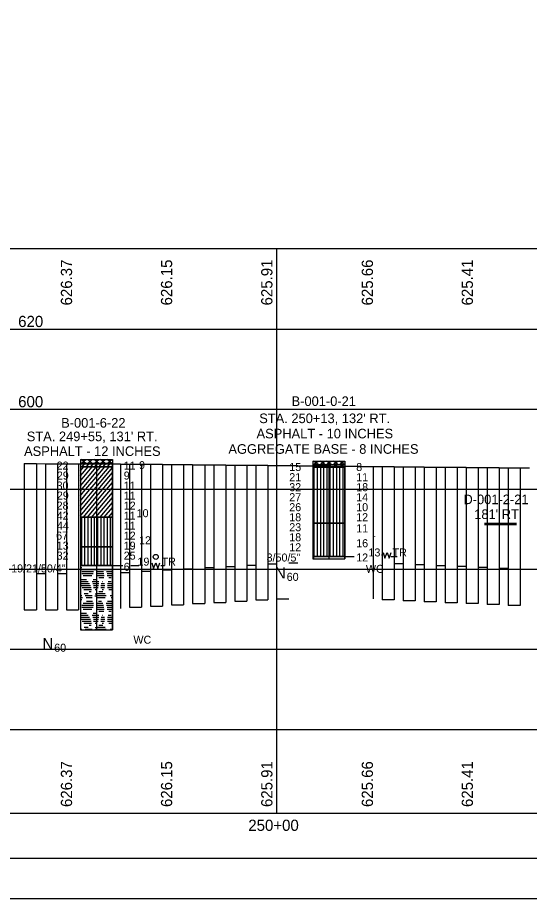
# Model space of a CAD drawing. Extents: x -2280229 to 1306, y -58886 to 440.
# Drawn here: x 120.3 to 248, y 0 to 220 of the extents above; entities that cross this region are included whole.
import ezdxf

# ---------------------------------------------------------------- set-up
doc = ezdxf.new("R2010")
doc.units = 0
for name, color, linetype in [('BR_P_Sub_Deep_Object', 7, 'Continuous'), ('GT_Project_Cells', 7, 'Continuous'), ('GT_Project_Soil_Layers', 7, 'Continuous'), ('GT_Project_Text', 7, 'Continuous'), ('SC_Scratch1', 7, 'Continuous'), ('SC_Scratch2', 7, 'Continuous'), ('SC_Scratch3', 7, 'Continuous'), ('SC_Scratch5', 7, 'Continuous'), ('SC_Scratch9', 7, 'Continuous'), ('SH_Minor_Grid_Line', 7, 'Continuous')]:
    doc.layers.add(name, color=color, linetype=linetype)

msp = doc.modelspace()

# ---------------------------------------------------------------- linework, layer by layer
at = {"layer": 'BR_P_Sub_Deep_Object'}
for p, q in [((121.98, 108.59), (121.98, 72.11)), ((121.98, 108.59), (124.98, 108.59)), ((124.98, 108.59), (124.98, 72.11)), ((124.98, 108.59), (127.23, 108.58)), ((127.23, 108.58), (127.23, 72.11)), ((127.23, 108.58), (130.23, 108.58)), ((130.23, 108.58), (130.23, 72.11)), ((132.48, 108.58), (132.48, 72.11)), ((132.48, 108.58), (135.48, 108.58)), ((135.48, 108.58), (135.48, 72.11)), ((135.48, 108.58), (137.73, 108.58)), ((137.73, 108.55), (140.73, 108.55)), ((140.73, 108.53), (142.98, 108.53)), ((142.98, 108.51), (145.98, 108.51)), ((145.98, 108.51), (145.98, 72.42)), ((145.98, 108.48), (148.23, 108.48)), ((148.23, 108.48), (148.23, 72.72)), ((148.23, 108.46), (151.23, 108.46)), ((151.23, 108.46), (151.23, 72.72)), ((151.23, 108.44), (153.48, 108.44)), ((153.48, 108.44), (153.48, 73.03)), ((153.48, 108.42), (156.48, 108.42)), ((156.48, 108.42), (156.48, 73.03)), ((156.48, 108.39), (158.73, 108.39)), ((158.73, 108.39), (158.73, 73.33)), ((158.73, 108.37), (161.73, 108.37)), ((161.73, 108.37), (161.73, 73.33)), ((161.73, 108.34), (163.98, 108.34)), ((163.98, 108.34), (163.98, 73.64)), ((163.98, 108.32), (166.98, 108.32)), ((166.98, 108.32), (166.98, 73.64)), ((166.98, 108.29), (169.23, 108.29)), ((169.23, 108.29), (169.23, 73.94)), ((169.23, 108.27), (172.23, 108.27)), ((172.23, 108.27), (172.23, 73.94)), ((172.23, 108.24), (174.48, 108.24)), ((174.48, 108.24), (174.48, 74.24)), ((174.48, 108.22), (177.48, 108.22)), ((177.48, 108.22), (177.48, 74.24)), ((177.48, 108.19), (179.73, 108.19)), ((179.73, 108.19), (179.73, 74.55)), ((179.73, 108.17), (182.73, 108.17)), ((182.73, 108.17), (182.73, 74.55)), ((182.73, 108.14), (184.98, 108.14)), ((184.98, 74.85), (184.98, 108.14)), ((184.98, 108.12), (187.98, 108.12)), ((187.98, 108.09), (190.23, 108.09)), ((190.23, 108.07), (193.23, 108.07)), ((193.23, 108.04), (195.48, 108.04)), ((195.48, 108.01), (198.48, 108.01)), ((198.48, 107.98), (200.73, 107.98)), ((200.73, 107.96), (203.73, 107.96)), ((208.98, 107.91), (208.98, 74.8)), ((211.23, 107.88), (211.23, 74.56)), ((211.23, 107.86), (214.23, 107.86)), ((214.23, 107.86), (214.23, 74.56)), ((214.23, 107.83), (216.48, 107.83)), ((216.48, 107.83), (216.48, 74.33)), ((216.48, 107.8), (219.48, 107.8)), ((219.48, 107.8), (219.48, 74.33)), ((219.48, 107.77), (221.73, 107.77)), ((221.73, 107.77), (221.73, 74.1)), ((221.73, 107.75), (224.73, 107.75)), ((224.73, 107.75), (224.73, 74.1)), ((224.73, 107.72), (226.98, 107.72)), ((226.98, 107.72), (226.98, 73.86)), ((226.98, 107.7), (229.98, 107.7)), ((229.98, 107.7), (229.98, 73.86)), ((229.98, 107.67), (232.23, 107.67)), ((232.23, 107.67), (232.23, 73.63)), ((232.23, 107.65), (235.23, 107.65)), ((235.23, 107.65), (235.23, 73.63)), ((235.23, 107.62), (237.48, 107.62)), ((237.48, 107.62), (237.48, 73.39)), ((237.48, 107.6), (240.48, 107.6)), ((240.48, 107.6), (240.48, 73.39)), ((240.48, 107.58), (242.73, 107.58)), ((242.73, 107.58), (242.73, 73.16)), ((242.73, 107.57), (245.73, 107.57)), ((245.73, 107.57), (245.73, 73.16)), ((245.73, 107.55), (247.98, 107.55)), ((187.98, 83.85), (190.23, 83.85)), ((156.48, 82.03), (158.73, 82.03)), ((161.73, 82.33), (163.98, 82.33)), ((166.98, 82.64), (169.23, 82.64)), ((172.23, 82.94), (174.48, 82.94)), ((177.48, 83.24), (179.73, 83.24)), ((182.73, 83.55), (184.98, 83.55)), ((216.48, 83.56), (214.23, 83.56)), ((221.73, 83.33), (219.48, 83.33)), ((226.98, 83.1), (224.73, 83.1)), ((232.23, 82.86), (229.98, 82.86)), ((237.48, 82.63), (235.23, 82.63)), ((242.73, 82.39), (240.48, 82.39)), ((247.98, 82.16), (245.73, 82.16)), ((124.98, 81.11), (127.23, 81.11)), ((130.23, 81.11), (132.48, 81.11)), ((184.98, 74.85), (187.98, 74.85)), ((148.23, 72.72), (151.23, 72.72)), ((153.48, 73.03), (156.48, 73.03)), ((158.73, 73.33), (161.73, 73.33)), ((163.98, 73.64), (166.98, 73.64)), ((169.23, 73.94), (172.23, 73.94)), ((174.48, 74.24), (177.48, 74.24)), ((179.73, 74.55), (182.73, 74.55)), ((214.23, 74.56), (211.23, 74.56)), ((219.48, 74.33), (216.48, 74.33)), ((224.73, 74.1), (221.73, 74.1)), ((229.98, 73.86), (226.98, 73.86)), ((235.23, 73.63), (232.23, 73.63)), ((240.48, 73.39), (237.48, 73.39)), ((245.73, 73.16), (242.73, 73.16)), ((121.98, 72.11), (124.98, 72.11)), ((127.23, 72.11), (130.23, 72.11)), ((132.48, 72.11), (135.48, 72.11))]:
    msp.add_line(p, q, dxfattribs=at)
at = {"layer": 'GT_Project_Cells'}
for points in [[(211.52, 86.42), (211.94, 85.02), (212.49, 86.42), (213.04, 85.02), (213.48, 86.42)], [(153.81, 83.82), (154.23, 82.42), (154.78, 83.82), (155.33, 82.42), (155.77, 83.82)]]:
    msp.add_lwpolyline(points, dxfattribs=at)
msp.add_circle((154.76, 85.31), 0.625, dxfattribs=at)
at = {"layer": 'GT_Project_Soil_Layers'}
for p, q in [((135.98, 108.61), (135.98, 108.61)), ((135.98, 108.5), (136.07, 108.61)), ((135.98, 106.78), (136.85, 107.81)), ((135.98, 105.53), (137.89, 107.81)), ((135.98, 104.29), (138.94, 107.81)), ((136.17, 108.61), (137.33, 109.61)), ((137.33, 108.61), (136.17, 109.61)), ((136.45, 107.81), (136.78, 108.21)), ((136.78, 108.21), (137.12, 108.61)), ((137.49, 107.81), (137.83, 108.21)), ((137.79, 108.61), (138.94, 109.61)), ((138.94, 108.61), (137.79, 109.61)), ((137.83, 108.21), (138.16, 108.61)), ((138.54, 107.81), (138.87, 108.21)), ((138.87, 108.21), (139.21, 108.61)), ((139.4, 108.61), (140.56, 109.61)), ((140.56, 108.61), (139.4, 109.61)), ((139.58, 107.81), (139.92, 108.21)), ((139.92, 108.21), (140.25, 108.61)), ((139.92, 107.73), (139.98, 107.81)), ((139.92, 106.48), (141.03, 107.81)), ((139.92, 105.24), (142.07, 107.81)), ((139.92, 103.99), (143.12, 107.81)), ((140.63, 107.81), (140.96, 108.21)), ((140.96, 108.21), (141.3, 108.61)), ((141.02, 108.61), (142.18, 109.61)), ((142.18, 108.61), (141.02, 109.61)), ((141.67, 107.81), (142.01, 108.21)), ((142.01, 108.21), (142.34, 108.61)), ((142.64, 108.61), (143.79, 109.61)), ((143.79, 108.61), (142.64, 109.61)), ((142.72, 107.81), (143.05, 108.21)), ((143.05, 108.21), (143.39, 108.61)), ((143.76, 107.81), (143.98, 108.07)), ((193.98, 108.41), (193.98, 108.41)), ((194.17, 108.41), (195.33, 109.21)), ((195.33, 108.41), (194.17, 109.21)), ((194.17, 107.71), (195.33, 108.41)), ((195.33, 107.71), (194.17, 108.41)), ((195.79, 108.41), (196.94, 109.21)), ((196.94, 108.41), (195.79, 109.21)), ((195.79, 107.71), (196.94, 108.41)), ((196.94, 107.71), (195.79, 108.41)), ((197.41, 108.41), (198.56, 109.21)), ((198.56, 108.41), (197.41, 109.21)), ((197.41, 107.71), (198.56, 108.41)), ((198.56, 107.71), (197.41, 108.41)), ((199.02, 108.41), (200.18, 109.21)), ((200.18, 108.41), (199.02, 109.21)), ((199.02, 107.71), (200.18, 108.41)), ((200.18, 107.71), (199.02, 108.41)), ((200.64, 108.41), (201.79, 109.21)), ((201.79, 108.41), (200.64, 109.21)), ((200.64, 107.71), (201.79, 108.41)), ((201.79, 107.71), (200.64, 108.41)), ((135.98, 103.05), (139.91, 107.73)), ((135.98, 101.8), (139.91, 106.48)), ((139.92, 102.75), (143.98, 107.6)), ((139.92, 101.51), (143.98, 106.35)), ((193.98, 107.71), (193.98, 107.71)), ((194.32, 100.71), (194.32, 107.71)), ((195.12, 100.71), (195.12, 107.71)), ((195.92, 100.71), (195.92, 107.71)), ((196.72, 100.71), (196.72, 107.71)), ((197.52, 100.71), (197.52, 107.71)), ((198.32, 100.71), (198.32, 107.71)), ((199.12, 100.71), (199.12, 107.71)), ((199.92, 100.71), (199.92, 107.71)), ((200.72, 100.71), (200.72, 107.71)), ((201.52, 100.71), (201.52, 107.71)), ((136.78, 101.51), (139.91, 105.24)), ((137.83, 101.51), (139.91, 103.99)), ((140.96, 101.51), (143.98, 105.11)), ((142.01, 101.51), (143.98, 103.86)), ((135.98, 100.56), (136.78, 101.51)), ((135.98, 99.31), (137.83, 101.51)), ((135.98, 98.07), (138.87, 101.51)), ((135.98, 96.82), (139.92, 101.51)), ((138.87, 101.51), (139.91, 102.75)), ((139.92, 97.77), (143.05, 101.51)), ((139.92, 99.02), (142.01, 101.51)), ((139.92, 100.26), (140.96, 101.51)), ((139.92, 96.53), (143.98, 101.37)), ((143.05, 101.51), (143.98, 102.62)), ((135.98, 95.58), (139.91, 100.26)), ((136.72, 95.21), (139.91, 99.02)), ((139.92, 95.28), (143.98, 100.13)), ((194.32, 93.71), (194.32, 100.71)), ((195.12, 93.71), (195.12, 100.71)), ((195.92, 93.71), (195.92, 100.71)), ((196.72, 93.71), (196.72, 100.71)), ((197.52, 93.71), (197.52, 100.71)), ((198.32, 93.71), (198.32, 100.71)), ((199.12, 93.71), (199.12, 100.71)), ((199.92, 93.71), (199.92, 100.71)), ((200.72, 93.71), (200.72, 100.71)), ((201.52, 93.71), (201.52, 100.71)), ((137.76, 95.21), (139.91, 97.77)), ((140.9, 95.21), (143.98, 98.88)), ((141.94, 95.21), (143.98, 97.64)), ((136.32, 91.51), (136.32, 95.21)), ((137.12, 91.51), (137.12, 95.21)), ((137.92, 91.51), (137.92, 95.21)), ((138.72, 91.51), (138.72, 95.21)), ((138.81, 95.21), (139.91, 96.53)), ((139.52, 91.51), (139.52, 95.21)), ((139.85, 95.21), (139.91, 95.28)), ((140.32, 91.51), (140.32, 95.21)), ((141.12, 91.51), (141.12, 95.21)), ((141.92, 91.51), (141.92, 95.21)), ((142.72, 91.51), (142.72, 95.21)), ((142.99, 95.21), (143.98, 96.4)), ((143.52, 91.51), (143.52, 95.21)), ((194.32, 89.56), (194.32, 93.71)), ((195.12, 89.56), (195.12, 93.71)), ((195.92, 89.56), (195.92, 93.71)), ((196.72, 89.56), (196.72, 93.71)), ((197.52, 89.56), (197.52, 93.71)), ((198.32, 89.56), (198.32, 93.71)), ((199.12, 89.56), (199.12, 93.71)), ((199.92, 89.56), (199.92, 93.71)), ((200.72, 89.56), (200.72, 93.71)), ((201.52, 89.56), (201.52, 93.71)), ((136.32, 87.81), (136.32, 91.51)), ((137.12, 87.81), (137.12, 91.51)), ((137.92, 87.81), (137.92, 91.51)), ((138.72, 87.81), (138.72, 91.51)), ((139.52, 87.81), (139.52, 91.51)), ((140.32, 87.81), (140.32, 91.51)), ((141.12, 87.81), (141.12, 91.51)), ((141.92, 87.81), (141.92, 91.51)), ((142.72, 87.81), (142.72, 91.51)), ((143.52, 87.81), (143.52, 91.51)), ((194.32, 85.41), (194.32, 89.56)), ((195.12, 85.41), (195.12, 89.56)), ((195.92, 85.41), (195.92, 89.56)), ((196.72, 85.41), (196.72, 89.56)), ((197.52, 85.41), (197.52, 89.56)), ((198.32, 85.41), (198.32, 89.56)), ((199.12, 85.41), (199.12, 89.56)), ((199.92, 85.41), (199.92, 89.56)), ((200.72, 85.41), (200.72, 89.56)), ((201.52, 85.41), (201.52, 89.56)), ((136.32, 85.46), (136.32, 87.81)), ((137.12, 85.46), (137.12, 87.81)), ((137.92, 85.46), (137.92, 87.81)), ((138.72, 85.46), (138.72, 87.81)), ((139.52, 85.46), (139.52, 87.81)), ((140.32, 85.46), (140.32, 87.81)), ((141.12, 85.46), (141.12, 87.81)), ((141.92, 85.46), (141.92, 87.81)), ((142.72, 85.46), (142.72, 87.81)), ((143.52, 85.46), (143.52, 87.81)), ((136.32, 83.11), (136.32, 85.46)), ((137.12, 83.11), (137.12, 85.46)), ((137.92, 83.11), (137.92, 85.46)), ((138.72, 83.11), (138.72, 85.46)), ((139.52, 83.11), (139.52, 85.46)), ((140.32, 83.11), (140.32, 85.46)), ((141.12, 83.11), (141.12, 85.46)), ((141.92, 83.11), (141.92, 85.46)), ((142.72, 83.11), (142.72, 85.46)), ((143.52, 83.11), (143.52, 85.46)), ((194.32, 85.04), (193.98, 85.04)), ((136.48, 83.04), (135.98, 83.04)), ((136.32, 82.54), (135.98, 82.54)), ((139.26, 81.54), (136.35, 81.54)), ((139.28, 82.04), (136.66, 82.04)), ((138.95, 83.04), (137.38, 83.04)), ((139.03, 82.17), (137.46, 82.17)), ((141.72, 81.54), (140.05, 81.54)), ((141.56, 82.04), (140.1, 82.04)), ((142.13, 83.04), (140.13, 83.04)), ((141.23, 82.17), (140.45, 82.17)), ((143.98, 82.04), (142.37, 82.04)), ((143.98, 81.54), (142.5, 81.54)), ((143.88, 82.17), (142.72, 82.17)), ((143.98, 83.04), (143.65, 83.04)), ((137.51, 79.54), (136.03, 79.54)), ((139.16, 81.04), (136.37, 81.04)), ((138.86, 80.54), (136.66, 80.54)), ((139.88, 79.54), (139.16, 79.54)), ((140.12, 79.54), (139.88, 79.54)), ((141.85, 81.04), (139.99, 81.04)), ((141.92, 80.54), (139.99, 80.54)), ((141.78, 80.04), (140.55, 80.04)), ((143.98, 81.04), (142.62, 81.04)), ((143.98, 80.54), (142.66, 80.54)), ((143.65, 80.04), (143.1, 80.04)), ((137.93, 79.04), (135.98, 79.04)), ((138.26, 78.54), (135.98, 78.54)), ((138.49, 78.04), (136.12, 78.04)), ((138.65, 77.54), (136.39, 77.54)), ((138.73, 77.04), (136.87, 77.04)), ((139.88, 79.04), (138.93, 79.04)), ((139.88, 78.54), (139.05, 78.54)), ((139.88, 78.04), (139.24, 78.04)), ((139.88, 77.54), (139.25, 77.54)), ((139.88, 77.04), (139.63, 77.04)), ((140.58, 79.04), (139.88, 79.04)), ((140.59, 78.54), (139.88, 78.54)), ((140.48, 78.04), (139.88, 78.04)), ((140.37, 77.54), (139.88, 77.54)), ((140.19, 77.04), (139.88, 77.04)), ((142.06, 78.04), (141.04, 78.04)), ((142.02, 77.54), (141.05, 77.54)), ((141.95, 78.54), (141.17, 78.54)), ((141.72, 77.04), (141.42, 77.04)), ((141.58, 79.04), (141.49, 79.04)), ((143.96, 78.54), (142.72, 78.54)), ((143.98, 77.54), (142.74, 77.54)), ((143.98, 78.04), (142.75, 78.04)), ((143.64, 79.04), (142.9, 79.04)), ((143.98, 77.04), (143.03, 77.04)), ((136.09, 76.04), (135.98, 76.04)), ((136.34, 75.54), (135.98, 75.54)), ((136.48, 75.04), (135.98, 75.04)), ((137.95, 76.04), (136.89, 76.04)), ((138.89, 75.54), (137.13, 75.54)), ((138.95, 75.04), (137.38, 75.04)), ((138.68, 76.54), (138.16, 76.54)), ((139.59, 75.54), (139.88, 75.54)), ((139.65, 76.04), (139.88, 76.04)), ((142.16, 76.04), (139.88, 76.04)), ((142.42, 75.54), (139.88, 75.54)), ((142.13, 75.04), (140.13, 75.04)), ((141.57, 76.54), (140.61, 76.54)), ((143.98, 75.54), (143.38, 75.54)), ((143.98, 75.04), (143.65, 75.04)), ((143.98, 76.04), (143.82, 76.04)), ((136.32, 74.54), (135.98, 74.54)), ((139.26, 73.17), (136.35, 73.17)), ((139.16, 72.67), (136.37, 72.67)), ((139.28, 73.67), (136.66, 73.67)), ((139.03, 74.17), (137.46, 74.17)), ((141.85, 72.67), (139.99, 72.67)), ((141.72, 73.17), (140.05, 73.17)), ((141.56, 73.67), (140.1, 73.67)), ((141.23, 74.17), (140.45, 74.17)), ((143.98, 73.67), (142.37, 73.67)), ((143.98, 73.17), (142.5, 73.17)), ((143.98, 72.67), (142.62, 72.67)), ((143.88, 74.17), (142.72, 74.17)), ((137.93, 70.67), (135.98, 70.67)), ((137.51, 71.17), (136.03, 71.17)), ((138.86, 72.17), (136.66, 72.17)), ((139.88, 70.67), (138.93, 70.67)), ((139.88, 71.17), (139.16, 71.17)), ((140.12, 71.17), (139.88, 71.17)), ((140.58, 70.67), (139.88, 70.67)), ((141.92, 72.17), (139.99, 72.17)), ((141.78, 71.67), (140.55, 71.67)), ((141.58, 70.67), (141.49, 70.67)), ((143.98, 72.17), (142.66, 72.17)), ((143.64, 70.67), (142.9, 70.67)), ((143.65, 71.67), (143.1, 71.67)), ((138.26, 70.17), (135.98, 70.17)), ((138.49, 69.67), (136.12, 69.67)), ((138.65, 69.17), (136.39, 69.17)), ((138.73, 68.67), (136.87, 68.67)), ((139.88, 70.17), (139.05, 70.17)), ((139.88, 69.67), (139.24, 69.67)), ((139.88, 69.17), (139.25, 69.17)), ((139.88, 68.67), (139.63, 68.67)), ((140.59, 70.17), (139.88, 70.17)), ((140.48, 69.67), (139.88, 69.67)), ((140.37, 69.17), (139.88, 69.17)), ((140.19, 68.67), (139.88, 68.67)), ((142.06, 69.67), (141.04, 69.67)), ((142.02, 69.17), (141.05, 69.17)), ((141.95, 70.17), (141.17, 70.17)), ((141.72, 68.67), (141.42, 68.67)), ((143.96, 70.17), (142.72, 70.17)), ((143.98, 69.17), (142.74, 69.17)), ((143.98, 69.67), (142.75, 69.67)), ((143.98, 68.67), (143.03, 68.67)), ((136.09, 67.67), (135.98, 67.67)), ((136.34, 67.17), (135.98, 67.17)), ((137.95, 67.67), (136.89, 67.67)), ((138.89, 67.17), (137.13, 67.17)), ((138.68, 68.17), (138.16, 68.17)), ((139.59, 67.17), (139.88, 67.17)), ((139.65, 67.67), (139.88, 67.67)), ((142.16, 67.67), (139.88, 67.67)), ((142.42, 67.17), (139.88, 67.17)), ((141.57, 68.17), (140.61, 68.17)), ((143.98, 67.17), (143.38, 67.17)), ((143.98, 67.67), (143.82, 67.67))]:
    msp.add_line(p, q, dxfattribs=at)
for points in [[(143.98, 108.61), (135.98, 108.61), (135.98, 107.81), (143.98, 107.81)], [(135.98, 95.21), (143.98, 95.21), (143.98, 107.81), (135.98, 107.81)], [(193.98, 93.71), (201.98, 93.71), (201.98, 107.71), (193.98, 107.71)], [(143.98, 95.21), (135.98, 95.21), (135.98, 87.81), (143.98, 87.81)], [(201.98, 93.71), (193.98, 93.71), (193.98, 85.41), (201.98, 85.41)], [(143.98, 87.81), (135.98, 87.81), (135.98, 83.11), (143.98, 83.11)], [(193.98, 84.81), (201.98, 84.81), (201.98, 85.41), (193.98, 85.41)], [(135.98, 82.11), (143.98, 82.11), (143.98, 83.11), (135.98, 83.11)], [(135.98, 67.11), (143.98, 67.11), (143.98, 82.11), (135.98, 82.11)]]:
    msp.add_lwpolyline(points, close=True, dxfattribs=at)
at = {"layer": 'GT_Project_Text'}
msp.add_lwpolyline([(0, 0), (680, 0), (680, 440), (0, 440)], close=True, dxfattribs=at)
at = {"layer": 'SC_Scratch1'}
msp.add_lwpolyline([(30, 430), (670, 430), (670, 10), (30, 10)], close=True, dxfattribs=at)
at = {"layer": 'SC_Scratch2'}
for p, q in [((130.23, 108.58), (132.48, 108.58)), ((135.98, 109.61), (143.98, 109.61)), ((135.98, 109.61), (135.98, 67.11)), ((135.98, 108.61), (143.98, 108.61)), ((135.98, 107.81), (143.98, 107.81)), ((139.98, 109.61), (139.98, 67.11)), ((143.98, 109.61), (143.98, 67.11)), ((193.98, 109.21), (201.98, 109.21)), ((193.98, 109.21), (193.98, 84.81)), ((193.98, 108.41), (201.98, 108.41)), ((197.98, 109.21), (197.98, 84.81)), ((201.98, 109.21), (201.98, 84.81)), ((201.98, 109.21), (201.98, 84.81)), ((203.73, 107.93), (205.98, 107.93)), ((205.98, 107.91), (208.98, 107.91)), ((208.98, 107.88), (211.23, 107.88)), ((193.98, 107.71), (201.98, 107.71)), ((135.98, 95.21), (143.98, 95.21)), ((193.98, 93.71), (201.98, 93.71)), ((236.8, 93.71), (244.8, 93.71)), ((236.8, 93.41), (244.8, 93.41)), ((240.8, 93.71), (240.8, 93.41)), ((135.98, 87.81), (143.98, 87.81)), ((193.98, 85.41), (201.98, 85.41)), ((193.98, 84.81), (201.98, 84.81)), ((201.98, 85.41), (204.27, 85.41)), ((211.46, 85.71), (211.06, 85.71)), ((135.98, 83.11), (143.98, 83.11)), ((135.98, 82.11), (143.98, 82.11)), ((145.98, 81.42), (148.23, 81.42)), ((148.55, 83.11), (150.53, 83.11)), ((151.23, 81.72), (153.48, 81.72)), ((135.98, 67.11), (143.98, 67.11))]:
    msp.add_line(p, q, dxfattribs=at)
at = {"layer": 'SC_Scratch3'}
for p, q in [((213.45, 85.41), (214.98, 85.41)), ((143.98, 83.11), (146.55, 83.11)), ((156.08, 83.11), (156.98, 83.11)), ((187.44, 81.31), (187.44, 81.31)), ((129.44, 63.61), (129.44, 63.61))]:
    msp.add_line(p, q, dxfattribs=at)
at = {"layer": 'SC_Scratch5'}
for p, q in [((603.01, 162.21), (45.43, 162.21)), ((603.01, 21.22), (45.43, 21.22))]:
    msp.add_line(p, q, dxfattribs=at)
at = {"layer": 'SH_Minor_Grid_Line'}
for p, q in [((184.98, 21.22), (184.98, 162.21)), ((45.43, 142.21), (603.01, 142.21)), ((45.43, 122.21), (603.01, 122.21)), ((45.43, 102.21), (603.01, 102.21)), ((45.43, 82.21), (603.01, 82.21)), ((45.43, 62.21), (603.01, 62.21)), ((45.43, 42.21), (603.01, 42.21))]:
    msp.add_line(p, q, dxfattribs=at)

# ---------------------------------------------------------------- texts
at = {"layer": 'SC_Scratch2'}
for s, height, p in [("STA. 250+13, 132' RT.", 2.4, (180.59, 118.71)), ("STA. 249+55, 131' RT.", 2.4, (122.59, 114.2)), ('22', 2, (130.05, 107.11)), ('11', 2, (146.78, 107.11)), ('9', 2, (150.61, 107.21)), ('15', 2, (188.08, 106.75)), ('8', 2, (204.78, 106.75)), ('29', 2, (130.1, 104.61)), ('9', 2, (146.78, 104.61)), ('21', 2, (188.08, 104.21)), ('11', 2, (204.78, 104.21)), ('30', 2, (130.04, 102.11)), ('11', 2, (146.78, 102.11)), ('32', 2, (188.08, 101.71)), ('18', 2, (204.78, 101.71)), ('29', 2, (130.1, 99.61)), ('11', 2, (146.78, 99.61)), ('27', 2, (188.08, 99.21)), ('14', 2, (204.78, 99.21)), ('28', 2, (130.05, 97.11)), ('12', 2, (146.78, 97.11)), ('10', 2, (150, 95.21)), ('26', 2, (188.08, 96.71)), ('10', 2, (204.78, 96.71)), ('42', 2, (130.05, 94.61)), ('11', 2, (146.78, 94.61)), ('18', 2, (188.08, 94.21)), ('12', 2, (204.78, 94.21)), ('44', 2, (130.12, 92.11)), ('11', 2, (146.78, 92.11)), ('23', 2, (188.08, 91.71)), ('11', 2, (204.78, 91.42)), ('67', 2, (129.92, 89.61)), ('12', 2, (146.78, 89.61)), ('12', 2, (150.6, 88.46)), ('18', 2, (188.08, 89.21)), ('-', 2, (208.75, 89.58)), ('13', 2, (130.07, 87.11)), ('19', 2, (146.78, 87.11)), ('12', 2, (188.08, 86.71)), ('16', 2, (204.78, 87.71)), ('25', 2, (146.78, 84.61)), ('3/50/5"', 2, (182.43, 84.14)), ('12', 2, (204.78, 84.15)), ('13', 2, (207.84, 85.41)), ('TR', 2, (213.86, 85.41)), ('6', 2, (146.78, 81.82)), ('19', 2, (150.21, 83.11)), ('TR', 2, (156.23, 83.11)), ('19/21/50/4"', 2, (118.7, 81.42))]:
    msp.add_text(s, height=height, dxfattribs=at).set_placement(p)
at = {"layer": 'SC_Scratch3'}
for s, height, p in [('B-001-0-21', 2.4, (188.66, 122.99)), ('B-001-6-22', 2.4, (131.17, 117.58)), ('ASPHALT - 10 INCHES', 2.4, (179.92, 114.9)), ('ASPHALT - 12 INCHES', 2.4, (121.92, 110.51)), ('AGGREGATE BASE - 8 INCHES', 2.4, (172.9, 111.05)), ('D-001-2-21', 2.4, (231.54, 98.46)), ("181' RT", 2.4, (234.23, 94.76)), ('N', 2.8, (184.5, 79.91)), ('60', 2, (187.44, 79.31)), ('N', 2.8, (126.5, 62.21)), ('60', 2, (129.44, 61.61))]:
    msp.add_text(s, height=height, dxfattribs=at).set_placement(p)
at = {"layer": 'SC_Scratch5'}
msp.add_text('32', height=2, dxfattribs=at).set_placement((130.05, 84.61))
at = {"layer": 'SC_Scratch9'}
for s, p in [('626.37', (133.9, 148.11)), ('626.15', (158.87, 148.11)), ('625.91', (183.88, 148.11)), ('625.66', (208.96, 148.11)), ('625.41', (233.9, 148.11)), ('626.37', (133.9, 22.82)), ('626.15', (158.87, 22.82)), ('625.91', (183.88, 22.82)), ('625.66', (208.96, 22.82)), ('625.41', (233.9, 22.82))]:
    msp.add_text(s, height=2.8, rotation=90, dxfattribs=at).set_placement(p)
for s, height, p in [('620', 2.8, (120.45, 142.71)), ('600', 2.8, (120.45, 122.68)), ('WC', 2, (207.2, 81.31)), ('WC', 2, (149.2, 63.61)), ('250+00', 2.8, (177.86, 16.86))]:
    msp.add_text(s, height=height, dxfattribs=at).set_placement(p)

doc.saveas('drawing.dxf')
